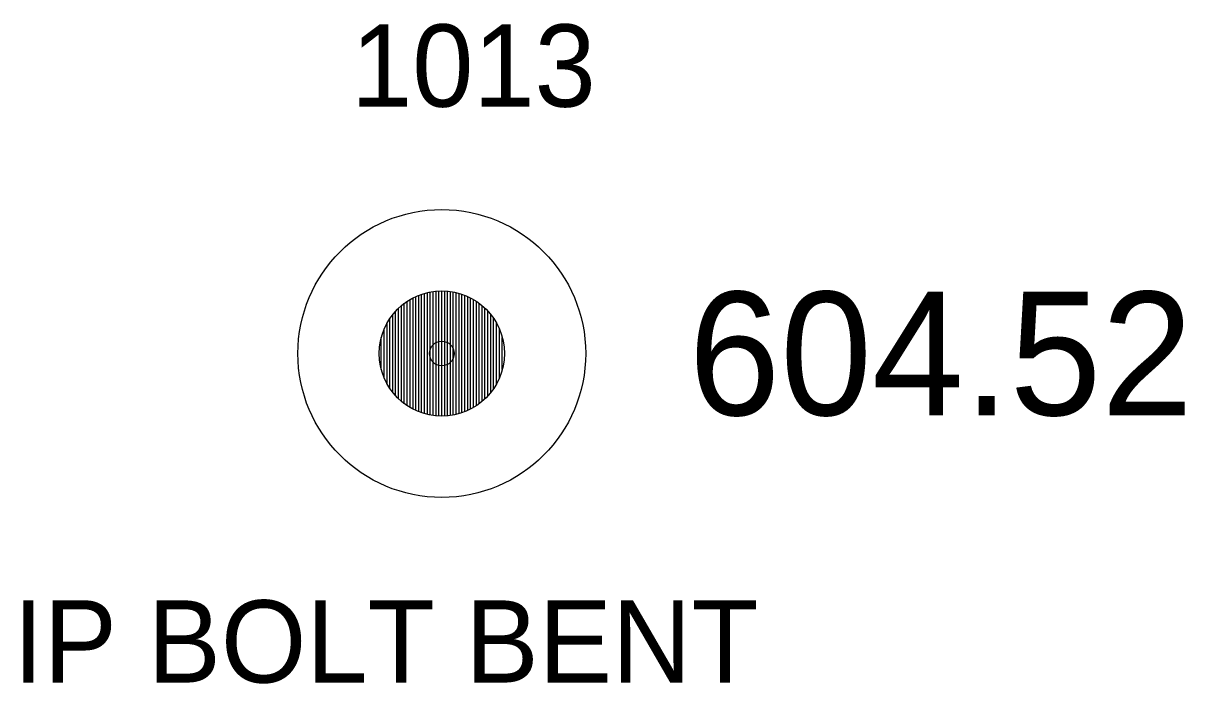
# Model space of a CAD drawing. Extents: x 1694813 to 1696862, y 1086485 to 1091027.
# Drawn here: x 1695609.44 to 1695623.56, y 1087942.87 to 1087950.9 of the extents above; entities that cross this region are included whole.
import ezdxf

# ---------------------------------------------------------------- set-up
doc = ezdxf.new("R2010")
doc.units = 0
for name, color, linetype in [('RD_EX_DV_Prop_txCode', 7, 'Continuous'), ('RD_EX_DV_PropPin', 7, 'Continuous'), ('RD_EX_TX_DV_Prop_ELEV', 7, 'Continuous'), ('RD_SMD_Locator', 7, 'Continuous')]:
    doc.layers.add(name, color=color, linetype=linetype)

msp = doc.modelspace()

# ---------------------------------------------------------------- linework, layer by layer
at = {"layer": 'RD_EX_DV_PropPin'}
for p, q in [((1695614.281, 1087946.163), (1695614.281, 1087947.604)), ((1695614.316, 1087946.152), (1695614.316, 1087947.615)), ((1695614.351, 1087946.143), (1695614.351, 1087947.624)), ((1695614.386, 1087946.136), (1695614.386, 1087947.632)), ((1695614.421, 1087946.13), (1695614.421, 1087947.637)), ((1695614.456, 1087946.126), (1695614.456, 1087947.641)), ((1695614.491, 1087946.123), (1695614.491, 1087947.644)), ((1695614.526, 1087946.123), (1695614.526, 1087947.645)), ((1695614.561, 1087946.123), (1695614.561, 1087947.644)), ((1695614.596, 1087946.126), (1695614.596, 1087947.641)), ((1695614.631, 1087946.13), (1695614.631, 1087947.637)), ((1695614.666, 1087946.136), (1695614.666, 1087947.632)), ((1695614.701, 1087946.143), (1695614.701, 1087947.624)), ((1695614.736, 1087946.152), (1695614.736, 1087947.615)), ((1695614.771, 1087946.163), (1695614.771, 1087947.604)), ((1695614.035, 1087946.302), (1695614.035, 1087947.466)), ((1695614.07, 1087946.274), (1695614.07, 1087947.494)), ((1695614.106, 1087946.249), (1695614.106, 1087947.518)), ((1695614.141, 1087946.227), (1695614.141, 1087947.54)), ((1695614.176, 1087946.208), (1695614.176, 1087947.559)), ((1695614.211, 1087946.191), (1695614.211, 1087947.576)), ((1695614.246, 1087946.176), (1695614.246, 1087947.591)), ((1695614.806, 1087946.176), (1695614.806, 1087947.591)), ((1695614.841, 1087946.191), (1695614.841, 1087947.576)), ((1695614.876, 1087946.208), (1695614.876, 1087947.559)), ((1695614.911, 1087946.227), (1695614.911, 1087947.54)), ((1695614.946, 1087946.249), (1695614.946, 1087947.518)), ((1695614.981, 1087946.274), (1695614.981, 1087947.494)), ((1695615.016, 1087946.302), (1695615.016, 1087947.466)), ((1695613.93, 1087946.41), (1695613.93, 1087947.358)), ((1695613.965, 1087946.369), (1695613.965, 1087947.399)), ((1695614, 1087946.333), (1695614, 1087947.434)), ((1695615.051, 1087946.333), (1695615.051, 1087947.434)), ((1695615.086, 1087946.369), (1695615.086, 1087947.399)), ((1695615.121, 1087946.41), (1695615.121, 1087947.358)), ((1695613.825, 1087946.586), (1695613.825, 1087947.182)), ((1695613.86, 1087946.514), (1695613.86, 1087947.253)), ((1695613.895, 1087946.457), (1695613.895, 1087947.31)), ((1695615.156, 1087946.457), (1695615.156, 1087947.31)), ((1695615.191, 1087946.514), (1695615.191, 1087947.253)), ((1695615.226, 1087946.586), (1695615.226, 1087947.182)), ((1695613.79, 1087946.688), (1695613.79, 1087947.08)), ((1695615.261, 1087946.688), (1695615.261, 1087947.08))]:
    msp.add_line(p, q, dxfattribs=at)
for radius in [1.75, 0.761]:
    msp.add_circle((1695614.526, 1087946.884), radius, dxfattribs=at)
at = {"layer": 'RD_SMD_Locator'}
msp.add_circle((1695614.526, 1087946.884), 0.15, dxfattribs=at)

# ---------------------------------------------------------------- texts
at = {"layer": 'RD_EX_DV_Prop_txCode'}
for s, p in [('1013', (1695613.423, 1087949.884)), ('IP BOLT BENT', (1695609.313, 1087942.884))]:
    msp.add_text(s, height=1, dxfattribs=at).set_placement(p)
at = {"layer": 'RD_EX_TX_DV_Prop_ELEV'}
msp.add_text('604.52', height=1.5, dxfattribs=at).set_placement((1695617.526, 1087946.134))

doc.saveas('drawing.dxf')
